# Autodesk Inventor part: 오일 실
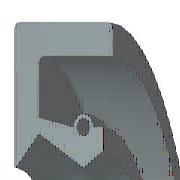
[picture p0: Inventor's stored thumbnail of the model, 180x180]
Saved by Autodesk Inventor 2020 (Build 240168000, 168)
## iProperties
IsCustomPart: 0
Created: 2009-02
Part Number: 오일 실
Material: 고무
Description: 오일-실
Document SubType Name: Modeling
Standard: KS B 2804
Designer: KYOUNG IL JANG
Standards Organization: KS
Language: ko-KR
Size Designation: D - 20 32 8
Categories: <MemberInstance><Categories><Category DisplayName="샤프트 부품" InternalName="7f7aeb1f-a693-4053-b835-cee3144e0d98" Mnemonic="SHFT"><Category DisplayName="실링" Intern
Density: 0.93 g/cm^3
Mass: 2.19344 g
Surface Area: 31.4782 cm^2
Volume: 2.35853 cm^3
Appearance: 고무 - 검은색 - 버전 1.1
Author: KYOUNG IL JANG
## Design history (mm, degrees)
revolve "본체" stored, may be unused: angle "d17" = 90 deg
revolve "스프링1" stored, may be unused: angle "d18" = 90 deg
body "Solid1"
sketch "스케치1"
  geometry: L1 (0, 16)-(8, 16); L2 (8, 14.25)-(1.75, 14.25); L3 (1.75, 11.75)-(4.9, 10); L4 (4.9, 10)-(0, 10); L5 (0, 0)-(9.586, 0) reference; L6 (4.9, 10)-(6.3, 10.875); L7 (0, 18)-(0, -3) reference; L8 (-1.941, 0)-(11.507, 0) reference; L9 (4.2, 12.1)-(1.75, 12.71); L10 (1.75, 12.71)-(1.75, 14.25); L11 (0, 16)-(0, 10.088); L12 (4.9, 10)-(0, 10); L13 (1.75, 11.75)-(0.152, 10.028); L14 (8, 16)-(8, 14.25); L15 (5.6, 12.1)-(6.3, 12.1); L16 (6.3, 12.1)-(6.3, 10.875); C1 r 0.455 at (4.9, 12.1); A1 r 0.7 centre (4.9, 12.1) between (5.6, 12.1) and (4.2, 12.1); A2 r 0.088 centre (0.088, 10.088) between (0, 10.088) and (0.152, 10.028); 1 further point
  constraints: 28 end point, 5 horizontal alignment, 5 point on line, 4 point on circle, 4 vertical alignment, 3 centre point, 3 tangent, 2 collinear, 2 horizontal, 2 perpendicular, 1 coincident, 1 parallel
  dimensions: "d0" = 32 diameter of L1 L5 (= SD2); "d1" = 1.75 distance of L1.end L2.start (= SD); "d2" = 0.91 diameter of C1 (= SPDI); "d3" = 1.4 diameter of A1 (= SPDA); "d4" = 20 diameter of L3.end L5 (= NND); "d5" = 23.5 diameter of L3.start L5 (= TKDM); "d7" = 25.42 diameter of L9.end L5 (= TKDM + 0.24 x SWDT); "d8" = 1.75 distance between parallel lines of L11 L10 (= SD); "d9" = 4.9 distance from line of L11 C1.centre (= SPDST); "d10" = 24.2 diameter of C1.centre L5 (= HLDM); "d11" = 0.0875 radius of A2 (= 0.25 x LAB); "d12" = 6.3 distance between parallel lines of L11 L16 (= SDI); "d13" = 21.75 diameter of L6.end L5 (= ABDM); "d14" = 8 distance from line of L11 L1.end (= SWDT)
fillet "모깎기1" dims "d6" = 0.3 (= RR)
other parameters: "SD2" = 32 [user parameter; used in 1 equation term], "SWDT" = 8 [user parameter; used in 2 equation terms], "RR" = 0.3 [user parameter; used in 1 equation term], "SD" = 1.75 [user parameter; used in 2 equation terms], "NND" = 20 [user parameter; used in 1 equation term], "SPDA" = 1.4 [user parameter; used in 1 equation term], "SPDI" = 0.91 [user parameter; used in 1 equation term], "TKDM" = 23.5 [user parameter; used in 2 equation terms], "HLDM" = 24.2 [user parameter; used in 1 equation term], "ABDM" = 21.75 [user parameter; used in 1 equation term], "SDI" = 6.3 [user parameter; used in 1 equation term], "SPDST" = 4.9 [user parameter; used in 1 equation term], "LAB" = 0.35 [user parameter; used in 1 equation term], "d15" = 0, "d16" = 0, "d19" = 0
